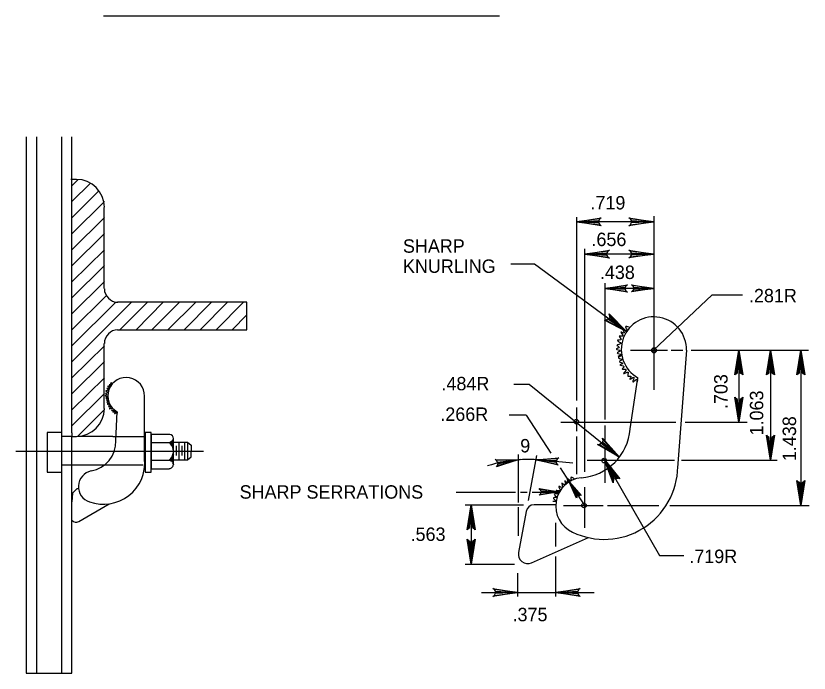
# Model space of a CAD drawing. Extents: x 150.3 to 157.3, y 91.3 to 101.4.
# Drawn here: x 150.522 to 154.068, y 95.448 to 98.387 of the extents above; entities that cross this region are included whole.
import ezdxf

# ---------------------------------------------------------------- set-up
doc = ezdxf.new("R2010")
doc.units = 0
for name, color, linetype in [('DETL-DIMS', 7, 'Continuous'), ('DETL-LINE', 7, 'Continuous'), ('DETL-NOTE', 7, 'Continuous'), ('DETL-PATT', 7, 'Continuous'), ('DETL-TITL', 7, 'Continuous')]:
    doc.layers.add(name, color=color, linetype=linetype)

msp = doc.modelspace()

# ---------------------------------------------------------------- linework, layer by layer
at = {"layer": 'DETL-DIMS'}
for p, q in [((153.0274, 97.4869), (153.0274, 96.6667)), ((153.3739, 97.4659), (153.0274, 97.4659)), ((153.3739, 97.491), (153.3739, 96.7152)), ((153.0636, 97.3446), (153.0636, 96.3482)), ((153.3739, 97.3218), (153.0636, 97.3218)), ((152.7351, 97.2787), (152.8401, 97.2787)), ((152.8401, 97.2787), (153.2537, 96.9742)), ((153.1546, 97.1913), (153.1546, 96.5827)), ((153.3739, 97.1684), (153.1551, 97.1684)), ((153.3727, 96.8925), (153.6349, 97.1396)), ((153.6349, 97.1396), (153.7708, 97.1396)), ((153.2695, 96.8925), (153.4346, 96.8925)), ((153.4515, 96.8925), (153.5034, 96.8925)), ((153.5407, 96.8925), (154.0651, 96.8925)), ((153.7536, 96.8925), (153.7536, 96.5699)), ((153.7536, 96.8925), (153.7536, 96.8902)), ((153.8954, 96.8925), (153.8954, 96.4002)), ((154.0313, 96.8925), (154.0313, 96.1977)), ((152.7485, 96.7403), (152.8162, 96.7403)), ((152.8162, 96.7403), (153.2199, 96.4142)), ((153.0274, 96.6358), (153.0274, 96.5297)), ((152.8036, 96.6008), (152.7277, 96.6008)), ((152.8036, 96.6008), (152.9131, 96.4311)), ((152.958, 96.5699), (153.4725, 96.5699)), ((153.028, 96.5699), (153.028, 96.5699)), ((153.1546, 96.5547), (153.1546, 96.4801)), ((153.5145, 96.5699), (153.7904, 96.5699)), ((153.0274, 96.5057), (153.0274, 96.3372)), ((151.3608, 96.4389), (150.5216, 96.4389)), ((153.1546, 96.4591), (153.1546, 96.2992)), ((152.7666, 96.4252), (152.7666, 96.2117)), ((152.8495, 96.4217), (152.8121, 96.2205)), ((152.9031, 96.399), (153.0122, 96.3879)), ((153.0764, 96.4002), (153.4655, 96.4002)), ((153.1511, 96.4042), (153.3996, 95.9737)), ((153.1546, 96.4013), (153.1546, 96.4013)), ((153.497, 96.4002), (153.9257, 96.4002)), ((152.9556, 96.3657), (152.9959, 96.3027)), ((152.9959, 96.3027), (153.0636, 96.1983)), ((152.4907, 96.2572), (152.7556, 96.2572)), ((152.7783, 96.2572), (152.8075, 96.2572)), ((152.8296, 96.2572), (152.9446, 96.2572)), ((153.0636, 96.28), (153.0636, 96.0974)), ((152.5304, 96.2007), (152.7911, 96.2007)), ((152.5572, 96.2007), (152.5572, 95.9352)), ((152.7666, 96.1896), (152.7666, 96.0618)), ((152.9696, 96.1977), (153.1476, 96.1977)), ((153.0636, 96.1983), (153.0636, 96.1983)), ((153.1668, 96.1977), (153.3961, 96.1977)), ((153.4451, 96.1977), (154.0681, 96.1977)), ((152.9335, 96.1202), (152.9335, 96.0146)), ((152.9335, 95.9691), (152.9335, 95.7912)), ((153.3996, 95.9737), (153.5086, 95.9737)), ((152.5304, 95.9352), (152.7515, 95.9352)), ((152.7643, 95.8956), (152.7643, 95.79)), ((152.6033, 95.8087), (152.7661, 95.8087)), ((152.7602, 95.8087), (152.9335, 95.8087)), ((152.9335, 95.8087), (153.1067, 95.8087))]:
    msp.add_line(p, q, dxfattribs=at)
for points in [[(153.1336, 97.4525), (153.1295, 97.4601), (153.0274, 97.4659), (153.1336, 97.4525), (153.1388, 97.4478), (153.0274, 97.4659), (153.1295, 97.4712), (153.133, 97.4787), (153.0274, 97.4659), (153.1388, 97.4834), (153.133, 97.4787)], [(153.2677, 97.4793), (153.2718, 97.4717), (153.3739, 97.4659), (153.2677, 97.4793), (153.2625, 97.484), (153.3739, 97.4659), (153.2718, 97.4607), (153.2683, 97.4531), (153.3739, 97.4659), (153.2625, 97.4484), (153.2683, 97.4531)], [(153.1697, 97.3084), (153.1656, 97.316), (153.0636, 97.3218), (153.1697, 97.3084), (153.175, 97.3037), (153.0636, 97.3218), (153.1656, 97.3271), (153.1691, 97.3347), (153.0636, 97.3218), (153.175, 97.3393), (153.1691, 97.3347)], [(153.2677, 97.3352), (153.2718, 97.3277), (153.3739, 97.3218), (153.2677, 97.3352), (153.2625, 97.3399), (153.3739, 97.3218), (153.2718, 97.3166), (153.2683, 97.309), (153.3739, 97.3218), (153.2625, 97.3043), (153.2683, 97.309)], [(153.2508, 97.1562), (153.2473, 97.1632), (153.1551, 97.1684), (153.2508, 97.1562), (153.2555, 97.1521), (153.1551, 97.1684), (153.2473, 97.1731), (153.2502, 97.1801), (153.1551, 97.1684), (153.2555, 97.1842), (153.2502, 97.1801)], [(153.2782, 97.1807), (153.2823, 97.1737), (153.3739, 97.1684), (153.2782, 97.1807), (153.2736, 97.1847), (153.3739, 97.1684), (153.2823, 97.1637), (153.2788, 97.1567), (153.3739, 97.1684), (153.2736, 97.1527), (153.2788, 97.1567)], [(153.1761, 97.0477), (153.175, 97.0389), (153.2537, 96.9742), (153.1761, 97.0477), (153.1744, 97.0547), (153.2537, 96.9742), (153.1686, 97.0307), (153.161, 97.0267), (153.2537, 96.9742), (153.1534, 97.0261), (153.161, 97.0267)], [(153.7402, 96.7863), (153.7478, 96.7904), (153.7536, 96.8925), (153.7402, 96.7863), (153.7356, 96.7811), (153.7536, 96.8925), (153.7589, 96.7904), (153.7665, 96.7869), (153.7536, 96.8925), (153.7711, 96.7811), (153.7665, 96.7869)], [(153.882, 96.7863), (153.8896, 96.7904), (153.8954, 96.8925), (153.882, 96.7863), (153.8773, 96.7811), (153.8954, 96.8925), (153.9006, 96.7904), (153.9082, 96.7869), (153.8954, 96.8925), (153.9129, 96.7811), (153.9082, 96.7869)], [(154.0179, 96.7863), (154.0255, 96.7904), (154.0313, 96.8925), (154.0179, 96.7863), (154.0132, 96.7811), (154.0313, 96.8925), (154.0366, 96.7904), (154.0441, 96.7869), (154.0313, 96.8925), (154.0488, 96.7811), (154.0441, 96.7869)], [(153.7671, 96.6761), (153.7595, 96.672), (153.7536, 96.5699), (153.7671, 96.6761), (153.7717, 96.6813), (153.7536, 96.5699), (153.7484, 96.672), (153.7408, 96.6755), (153.7536, 96.5699), (153.7361, 96.6813), (153.7408, 96.6755)], [(153.9088, 96.5063), (153.9012, 96.5022), (153.8954, 96.4002), (153.9088, 96.5063), (153.9135, 96.5116), (153.8954, 96.4002), (153.8901, 96.5022), (153.8826, 96.5057), (153.8954, 96.4002), (153.8779, 96.5116), (153.8826, 96.5057)], [(153.1458, 96.4912), (153.1441, 96.4824), (153.2199, 96.4142), (153.1458, 96.4912), (153.1446, 96.4982), (153.2199, 96.4142), (153.1376, 96.4742), (153.1301, 96.4707), (153.2199, 96.4142), (153.1219, 96.4702), (153.1301, 96.4707)], [(152.6698, 96.399), (152.6739, 96.392), (152.7661, 96.4013), (152.6698, 96.399), (152.6651, 96.4031), (152.7661, 96.4013), (152.6751, 96.3827), (152.6745, 96.3757), (152.7661, 96.4013), (152.6698, 96.3704), (152.6745, 96.3757)], [(152.9416, 96.3821), (152.9387, 96.3897), (152.8477, 96.4019), (152.9416, 96.3821), (152.9463, 96.378), (152.8477, 96.4019), (152.9399, 96.399), (152.9434, 96.406), (152.8477, 96.4019), (152.9492, 96.4101), (152.9434, 96.406)], [(153.1925, 96.3057), (153.1971, 96.3132), (153.1511, 96.4042), (153.1925, 96.3057), (153.1913, 96.2987), (153.1511, 96.4042), (153.2065, 96.3185), (153.2146, 96.3191), (153.1511, 96.4042), (153.2222, 96.3167), (153.2146, 96.3191)], [(153.0291, 96.2345), (153.0326, 96.2386), (152.9953, 96.3027), (153.0291, 96.2345), (153.0286, 96.2304), (152.9953, 96.3027), (153.0373, 96.2432), (153.0431, 96.2444), (152.9953, 96.3027), (153.0484, 96.2427), (153.0431, 96.2444)], [(154.0447, 96.3039), (154.0371, 96.2998), (154.0313, 96.1977), (154.0447, 96.3039), (154.0494, 96.3092), (154.0313, 96.1977), (154.0261, 96.2998), (154.0185, 96.3033), (154.0313, 96.1977), (154.0138, 96.3092), (154.0185, 96.3033)], [(152.8646, 96.2689), (152.8681, 96.2631), (152.9498, 96.2584), (152.8646, 96.2689), (152.8606, 96.273), (152.9498, 96.2584), (152.8681, 96.2543), (152.8652, 96.2479), (152.9498, 96.2584), (152.8606, 96.2444), (152.8652, 96.2479)], [(152.5438, 96.0945), (152.5514, 96.0986), (152.5572, 96.2007), (152.5438, 96.0945), (152.5391, 96.0892), (152.5572, 96.2007), (152.5625, 96.0986), (152.5701, 96.0951), (152.5572, 96.2007), (152.5747, 96.0892), (152.5701, 96.0951)], [(152.5706, 96.0414), (152.5631, 96.0373), (152.5572, 95.9352), (152.5706, 96.0414), (152.5753, 96.0467), (152.5572, 95.9352), (152.552, 96.0373), (152.5444, 96.0408), (152.5572, 95.9352), (152.5397, 96.0467), (152.5444, 96.0408)], [(152.6599, 95.8221), (152.664, 95.8145), (152.7661, 95.8087), (152.6599, 95.8221), (152.6546, 95.8267), (152.7661, 95.8087), (152.664, 95.8034), (152.6605, 95.7958), (152.7661, 95.8087), (152.6546, 95.7912), (152.6605, 95.7958)], [(153.0396, 95.7952), (153.0356, 95.8028), (152.9335, 95.8087), (153.0396, 95.7952), (153.0449, 95.7906), (152.9335, 95.8087), (153.0356, 95.8139), (153.0391, 95.8215), (152.9335, 95.8087), (153.0449, 95.8262), (153.0391, 95.8215)]]:
    msp.add_lwpolyline(points, dxfattribs=at)
for centre in [(153.3745, 96.8931), (153.3745, 96.8902), (153.0274, 96.5722), (153.1516, 96.3984), (153.0618, 96.1977)]:
    msp.add_circle(centre, 0.0101, dxfattribs=at)
for centre, radius, start, end in [((152.828, 95.7302), 0.6742, 94.2804, 107.1223), ((152.8116, 95.8227), 0.5806, 86.3698, 94.437), ((152.8116, 95.8227), 0.5806, 77.5339, 86.3698)]:
    msp.add_arc(centre, radius, start, end, dxfattribs=at)
at = {"layer": 'DETL-LINE'}
for p, q in [((150.5674, 97.8456), (150.5674, 95.4481)), ((150.6133, 97.8456), (150.6133, 95.4481)), ((150.7266, 95.4481), (150.7266, 97.8456)), ((150.7724, 96.5231), (150.7724, 97.8456)), ((150.7916, 97.6556), (150.7674, 97.6556)), ((150.9166, 97.1672), (150.9166, 97.5306)), ((151.5549, 97.1064), (150.9766, 97.1064)), ((151.5549, 96.9831), (151.5549, 97.1064)), ((150.9766, 96.9831), (151.5549, 96.9831)), ((150.9166, 96.6314), (150.9166, 96.9214)), ((153.5197, 96.8919), (153.4801, 96.3657)), ((153.2683, 96.5407), (153.3027, 96.7682)), ((153.3027, 96.7682), (153.3025, 96.7685)), ((151.0969, 96.4051), (151.0967, 96.686)), ((150.9687, 96.4871), (150.9746, 96.6165)), ((150.7258, 96.5247), (150.6616, 96.5247)), ((150.6616, 96.5247), (150.6616, 96.3464)), ((150.7266, 96.5072), (150.7724, 96.5072)), ((150.7724, 96.5231), (150.7724, 96.5064)), ((150.7724, 95.4481), (150.7724, 96.5064)), ((150.7724, 96.5064), (150.7916, 96.5064)), ((150.8041, 96.5072), (150.9549, 96.5072)), ((150.9549, 96.5064), (151.0974, 96.5064)), ((151.1266, 96.5247), (151.0999, 96.5247)), ((151.0999, 96.5247), (151.0999, 96.3464)), ((151.1266, 96.3464), (151.1266, 96.5247)), ((151.1266, 96.5147), (151.1266, 96.3622)), ((151.2091, 96.5147), (151.1266, 96.5147)), ((151.1266, 96.4797), (151.2008, 96.4797)), ((151.2008, 96.4797), (151.2058, 96.4797)), ((151.2058, 96.4789), (151.2066, 96.4797)), ((151.2074, 96.4789), (151.2091, 96.4797)), ((151.2091, 96.4764), (151.2133, 96.4806)), ((151.2091, 96.4772), (151.2099, 96.4797)), ((151.2099, 96.4756), (151.2166, 96.4831)), ((151.2108, 96.4747), (151.2258, 96.4889)), ((151.2116, 96.4747), (151.2258, 96.4872)), ((151.2133, 96.4731), (151.2258, 96.4856)), ((151.2133, 96.4714), (151.2258, 96.4839)), ((151.2141, 96.4706), (151.2258, 96.4814)), ((151.2141, 96.4706), (151.2258, 96.4797)), ((151.2158, 96.4689), (151.2258, 96.4789)), ((151.2166, 96.4681), (151.2258, 96.4764)), ((151.2174, 96.4664), (151.2258, 96.4747)), ((151.2183, 96.4664), (151.2258, 96.4731)), ((151.2183, 96.4647), (151.2258, 96.4706)), ((151.2191, 96.4631), (151.2258, 96.4689)), ((151.2199, 96.4622), (151.2258, 96.4672)), ((151.2208, 96.4606), (151.2258, 96.4664)), ((151.2224, 96.4881), (151.2258, 96.4906)), ((151.2241, 96.4914), (151.2258, 96.4922)), ((151.2258, 96.4422), (151.2258, 96.4981)), ((151.2258, 96.4956), (151.2258, 96.4964)), ((151.2258, 96.4956), (151.2258, 96.4964)), ((151.2258, 96.4939), (151.2258, 96.4939)), ((151.2258, 96.4806), (151.2883, 96.4806)), ((151.2383, 96.4647), (151.2383, 96.4206)), ((151.2508, 96.4806), (151.2508, 96.4022)), ((151.2641, 96.4647), (151.2641, 96.4206)), ((151.2758, 96.4806), (151.2758, 96.4022)), ((151.2883, 96.4806), (151.3049, 96.4672)), ((151.2883, 96.4806), (151.2883, 96.4022)), ((151.3049, 96.4672), (151.3049, 96.4414)), ((151.2216, 96.4597), (151.2258, 96.4639)), ((151.2216, 96.4581), (151.2258, 96.4622)), ((151.2224, 96.4564), (151.2258, 96.4606)), ((151.2224, 96.4564), (151.2258, 96.4581)), ((151.2224, 96.4547), (151.2258, 96.4564)), ((151.2233, 96.4539), (151.2258, 96.4547)), ((151.2241, 96.4522), (151.2258, 96.4539)), ((151.2241, 96.4497), (151.2258, 96.4514)), ((151.2241, 96.4497), (151.2258, 96.4497)), ((151.2241, 96.4289), (151.2258, 96.4272)), ((151.2241, 96.4289), (151.2258, 96.4289)), ((151.2249, 96.4472), (151.2258, 96.4481)), ((151.2249, 96.4314), (151.2258, 96.4306)), ((151.2258, 96.4422), (151.2258, 96.4356)), ((151.2258, 96.3806), (151.2258, 96.4356)), ((151.2258, 96.4356), (151.2258, 96.4356)), ((151.3049, 96.4147), (151.3049, 96.4414)), ((151.1266, 96.3997), (151.2008, 96.3997)), ((151.2008, 96.3997), (151.2058, 96.3997)), ((151.2058, 96.3997), (151.2066, 96.3981)), ((151.2074, 96.3997), (151.2091, 96.3981)), ((151.2091, 96.4022), (151.2133, 96.3981)), ((151.2091, 96.4006), (151.2099, 96.3981)), ((151.2099, 96.4022), (151.2166, 96.3964)), ((151.2108, 96.4039), (151.2258, 96.3897)), ((151.2116, 96.4039), (151.2258, 96.3914)), ((151.2133, 96.4064), (151.2258, 96.3956)), ((151.2133, 96.4056), (151.2258, 96.3931)), ((151.2141, 96.4081), (151.2258, 96.3981)), ((151.2141, 96.4081), (151.2258, 96.3964)), ((151.2158, 96.4097), (151.2258, 96.3997)), ((151.2166, 96.4106), (151.2258, 96.4022)), ((151.2174, 96.4122), (151.2258, 96.4039)), ((151.2183, 96.4131), (151.2258, 96.4081)), ((151.2183, 96.4122), (151.2258, 96.4056)), ((151.2191, 96.4147), (151.2258, 96.4089)), ((151.2199, 96.4164), (151.2258, 96.4106)), ((151.2208, 96.4172), (151.2258, 96.4122)), ((151.2216, 96.4206), (151.2258, 96.4164)), ((151.2216, 96.4189), (151.2258, 96.4147)), ((151.2224, 96.4247), (151.2258, 96.4214)), ((151.2224, 96.4231), (151.2258, 96.4206)), ((151.2224, 96.4214), (151.2258, 96.4181)), ((151.2233, 96.4256), (151.2258, 96.4231)), ((151.2241, 96.4264), (151.2258, 96.4247)), ((151.2258, 96.4022), (151.2883, 96.4022)), ((151.2883, 96.4022), (151.3049, 96.4147)), ((150.7266, 96.3789), (150.8408, 96.3789)), ((150.8408, 96.3789), (151.0908, 96.3789)), ((151.1266, 96.3622), (151.2074, 96.3622)), ((151.2224, 96.3897), (151.2258, 96.3872)), ((151.2241, 96.3872), (151.2258, 96.3856)), ((151.2258, 96.3839), (151.2258, 96.3839)), ((151.2258, 96.3831), (151.2258, 96.3814)), ((151.2258, 96.3814), (151.2258, 96.3806)), ((150.6616, 96.3464), (150.7258, 96.3464)), ((151.0999, 96.3464), (151.1266, 96.3464)), ((150.7755, 96.2531), (150.7724, 96.2142)), ((150.7936, 96.2718), (150.7755, 96.2531)), ((150.802, 96.2727), (150.7936, 96.2718)), ((150.8027, 96.1262), (150.9384, 96.2045)), ((152.9352, 96.2007), (152.8384, 96.2007)), ((152.8028, 96.1709), (152.769, 95.9877)), ((152.8273, 95.9417), (153.0816, 96.0548)), ((150.5674, 95.4481), (150.7724, 95.4481))]:
    msp.add_line(p, q, dxfattribs=at)
for centre, radius, start, end in [((150.7921, 97.5308), 0.125, 0, 90), ((150.978, 97.167), 0.0608, 180, 270), ((153.3739, 96.8954), 0.1456, 358.6252, 240.6548), ((150.978, 96.9223), 0.0608, 90, 180), ((151.0147, 96.6879), 0.082, 358.6252, 240.6548), ((150.7921, 96.6318), 0.125, 270, 0), ((153.0315, 96.5582), 0.2373, 274.0856, 355.4934), ((151.2078, 96.4975), 0.0179, 94.69861111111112, 94.6986138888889), ((151.2078, 96.4975), 0.0179, 357.2972, 85.3014), ((150.8351, 96.4836), 0.1336, 280.0856, 1.4934), ((151.2078, 96.4975), 0.0179, 265.7337, 354.61), ((151.1737, 96.4391), 0.0522, 9.0812, 51.0633), ((151.1737, 96.4398), 0.0522, 309.7217, 355.0029), ((151.1737, 96.4398), 0.0522, 4.1537, 9.0812), ((150.9129, 96.3878), 0.1848, 250.348, 5.3872), ((151.2076, 96.3809), 0.0181, 0, 93.6108), ((151.2078, 96.3808), 0.0179, 269.041, 2.7028), ((153.1522, 96.3745), 0.3283, 244.348, 359.3872), ((150.8731, 96.2818), 0.0717, 101.7365, 251.7963), ((153.0624, 96.1948), 0.1274, 95.7365, 245.7963), ((152.8386, 96.1643), 0.0364, 90, 169.2899), ((150.7908, 96.1465), 0.0236, 218.9868, 300.0163), ((152.8101, 95.9798), 0.042, 169.5085, 294.0163)]:
    msp.add_arc(centre, radius, start, end, dxfattribs=at)
for points in [[(153.2642, 96.9946), (153.2473, 96.9963), (153.2543, 96.9794), (153.2368, 96.9835), (153.2409, 96.9689), (153.2269, 96.9724), (153.2356, 96.9549), (153.2193, 96.9543), (153.2275, 96.9397), (153.21, 96.9357), (153.2257, 96.9222), (153.2088, 96.9135), (153.2193, 96.9047), (153.2059, 96.8972), (153.224, 96.889), (153.21, 96.8797), (153.2292, 96.8727), (153.2123, 96.8645)], [(153.2304, 96.8674), (153.2164, 96.8575), (153.2321, 96.8493), (153.2199, 96.8412), (153.2351, 96.833), (153.2216, 96.826), (153.2403, 96.819), (153.2316, 96.8079), (153.2491, 96.8056), (153.2386, 96.7875), (153.259, 96.7933), (153.2578, 96.7758), (153.2712, 96.7758), (153.266, 96.7612), (153.2846, 96.7712), (153.28, 96.7502), (153.2998, 96.763), (153.2975, 96.7461)], [(150.9539, 96.7435), (150.9444, 96.7444), (150.9483, 96.7349), (150.9384, 96.7372), (150.9407, 96.729), (150.9329, 96.731), (150.9378, 96.7211), (150.9286, 96.7208), (150.9332, 96.7126), (150.9233, 96.7103), (150.9322, 96.7027), (150.9227, 96.6978), (150.9286, 96.6929), (150.921, 96.6886), (150.9312, 96.684), (150.9233, 96.6788), (150.9342, 96.6748), (150.9341, 96.6743)], [(150.9349, 96.6744), (150.927, 96.6688), (150.9359, 96.6642), (150.929, 96.6596), (150.9375, 96.655), (150.93, 96.6511), (150.9405, 96.6471), (150.9356, 96.6409), (150.9454, 96.6396), (150.9395, 96.6294), (150.951, 96.6327), (150.9504, 96.6228), (150.9579, 96.6228), (150.955, 96.6146), (150.9655, 96.6202), (150.9628, 96.6084), (150.974, 96.6156), (150.9727, 96.6061)], [(153.0198, 96.315), (153.0029, 96.3226), (153.0029, 96.3074), (152.9877, 96.3156), (152.9877, 96.2981), (152.9766, 96.3086), (152.9766, 96.2893), (152.9621, 96.2969), (152.9656, 96.2777), (152.9486, 96.2823), (152.9551, 96.2637), (152.937, 96.2642), (152.9446, 96.2502), (152.9288, 96.2485), (152.9411, 96.2333), (152.9247, 96.2322), (152.937, 96.2164), (152.9224, 96.2158)]]:
    msp.add_spline(points, degree=3, dxfattribs=at)
at = {"layer": 'DETL-PATT'}
for p, q in [((150.7724, 97.6272), (150.8008, 97.6547)), ((150.7724, 97.5564), (150.8549, 97.6381)), ((150.7724, 97.4839), (150.8924, 97.6039)), ((150.7724, 97.4122), (150.9174, 97.5564)), ((150.7724, 97.3414), (150.9174, 97.4856)), ((150.7724, 97.2697), (150.9174, 97.4131)), ((150.7724, 97.1981), (150.9174, 97.3414)), ((150.7724, 97.1264), (150.9174, 97.2706)), ((150.7724, 97.0547), (150.9174, 97.1997)), ((150.7724, 96.9831), (150.9258, 97.1356)), ((150.7724, 96.9114), (150.9683, 97.1072)), ((150.7724, 96.8397), (151.0391, 97.1064)), ((150.9866, 96.9831), (151.1099, 97.1064)), ((151.0591, 96.9831), (151.1808, 97.1064)), ((151.1299, 96.9831), (151.2533, 97.1064)), ((151.2016, 96.9831), (151.3258, 97.1064)), ((151.2733, 96.9831), (151.3966, 97.1064)), ((151.3449, 96.9831), (151.4683, 97.1064)), ((151.4166, 96.9831), (151.5391, 97.1064)), ((151.4883, 96.9831), (151.5549, 97.0497)), ((150.7724, 96.7689), (150.9174, 96.9122)), ((150.7724, 96.6964), (150.9174, 96.8414)), ((150.7724, 96.6247), (150.9174, 96.7689)), ((150.7724, 96.5539), (150.9174, 96.6981)), ((150.7974, 96.5064), (150.9174, 96.6264))]:
    msp.add_line(p, q, dxfattribs=at)
at = {"layer": 'DETL-TITL'}
msp.add_line((150.9137, 98.3868), (152.6836, 98.3868), dxfattribs=at)

# ---------------------------------------------------------------- texts
at = {"layer": 'DETL-NOTE'}
for s, rotation, p in [('.719', 360, (153.0904, 97.5212)), ('SHARP', 360, (152.2521, 97.3276)), ('.656', 360, (153.0948, 97.3575)), ('KNURLING', 360, (152.2521, 97.2376)), ('.438', 360, (153.1325, 97.2102)), ('.281R', 360, (153.7991, 97.106)), ('.484R', 360, (152.4242, 96.7126)), ('.703', 90, (153.7033, 96.6288)), ('1.063', 90, (153.8631, 96.5109)), ('.266R', 360, (152.4192, 96.5759)), ('1.438', 90, (154.0096, 96.3958)), ('9', 360, (152.7765, 96.4349)), ('SHARP SERRATIONS', 360, (151.5221, 96.2281)), ('.563', 360, (152.2862, 96.0392)), ('.719R', 360, (153.5324, 95.9403)), ('.375', 360, (152.7421, 95.6801))]:
    msp.add_text(s, height=0.06, rotation=rotation, dxfattribs=at).set_placement(p)

doc.saveas('drawing.dxf')
